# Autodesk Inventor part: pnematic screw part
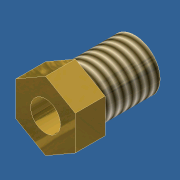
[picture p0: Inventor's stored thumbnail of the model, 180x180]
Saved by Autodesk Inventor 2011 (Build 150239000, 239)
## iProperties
Created: 2010-02
Part Number: pnematic screw part
Document SubType Name: Modeling
Designer: clee1
Density: 1 g/cm^3
Author: clee1
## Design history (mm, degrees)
sketch "Sketch1"
  geometry: C1 r 5.397 at (0, 0); 1 further point
  constraints: 1 centre point, 1 coincident
  dimensions: "d0" = 10.795 diameter of C1
extrude "Extrusion1" new body sketch "Sketch1" distance "d1" = 12.7; taper "d2" = 0 deg
thread "Thread1" dims "d3" = 25.4, "d4" = 0
sketch "Sketch2"
  geometry: L1 (0, 7.332)-(6.35, 3.666); L2 (6.35, 3.666)-(6.35, -3.666); L3 (6.35, -3.666)-(0, -7.332); L4 (0, -7.332)-(-6.35, -3.666); L5 (-6.35, -3.666)-(-6.35, 3.666); L6 (-6.35, 3.666)-(0, 7.332); C1 r 5.397 at (0, 0) reference; 1 further point
  constraints: 12 end point, 13 other
  dimensions: "d5" = 12.7 distance between parallel lines of L2 L5; "d6" = 0 distance of point (0, 0) C1.centre
extrude "Extrusion2" join sketch "Sketch2" distance "d7" = 6.35; taper "d8" = 0 deg
sketch "Sketch5"
  geometry: C1 r 3.175 at (0, 0); 1 further point
  constraints: 1 centre point, 1 coincident
  dimensions: "d14" = 6.35 diameter of C1
extrude "Extrusion5" cut sketch "Sketch5" stored distance "d15" = 25.4; taper "d16" = 0 deg
body "Solid1"
